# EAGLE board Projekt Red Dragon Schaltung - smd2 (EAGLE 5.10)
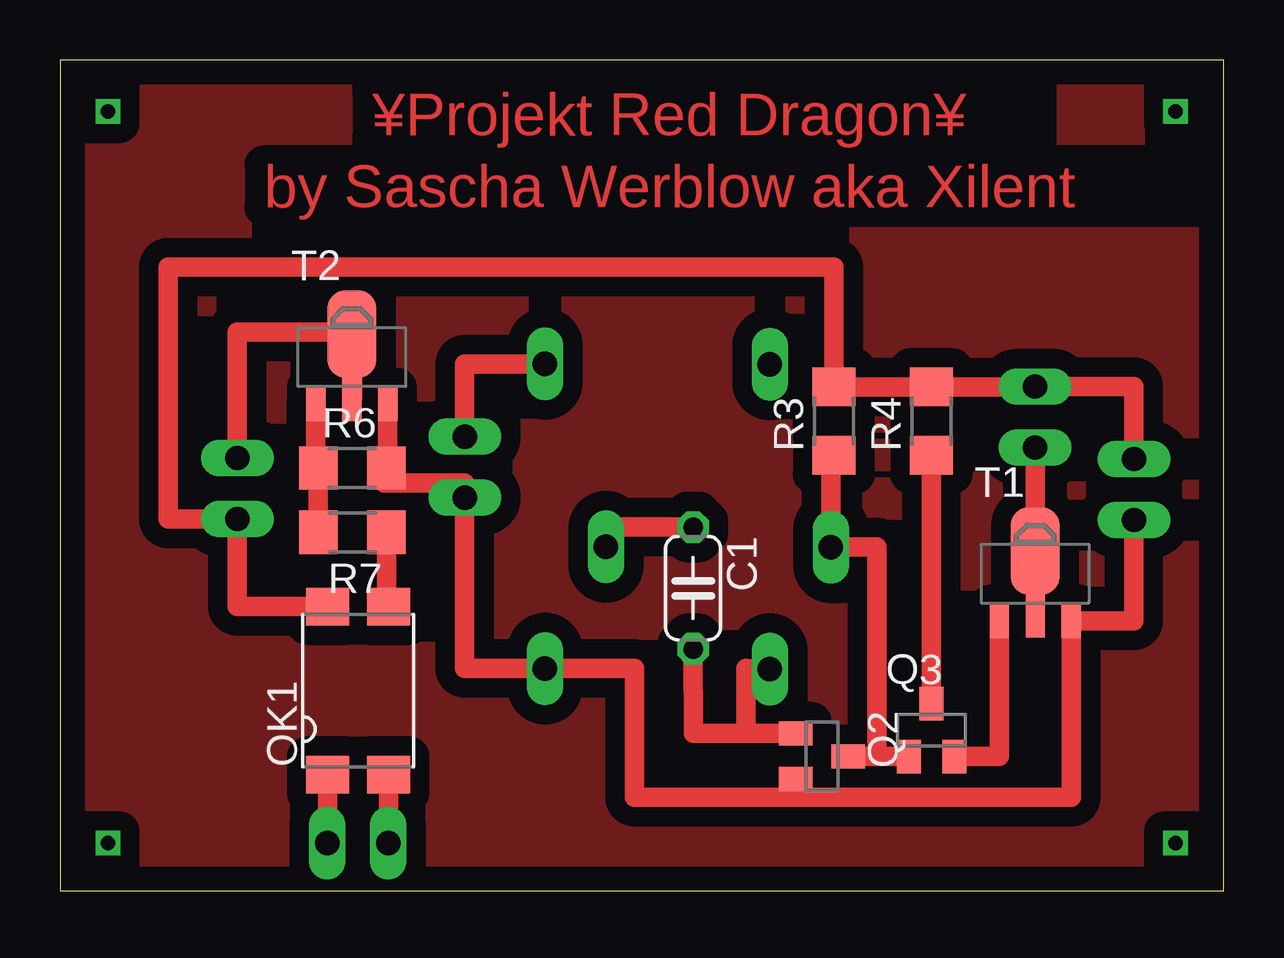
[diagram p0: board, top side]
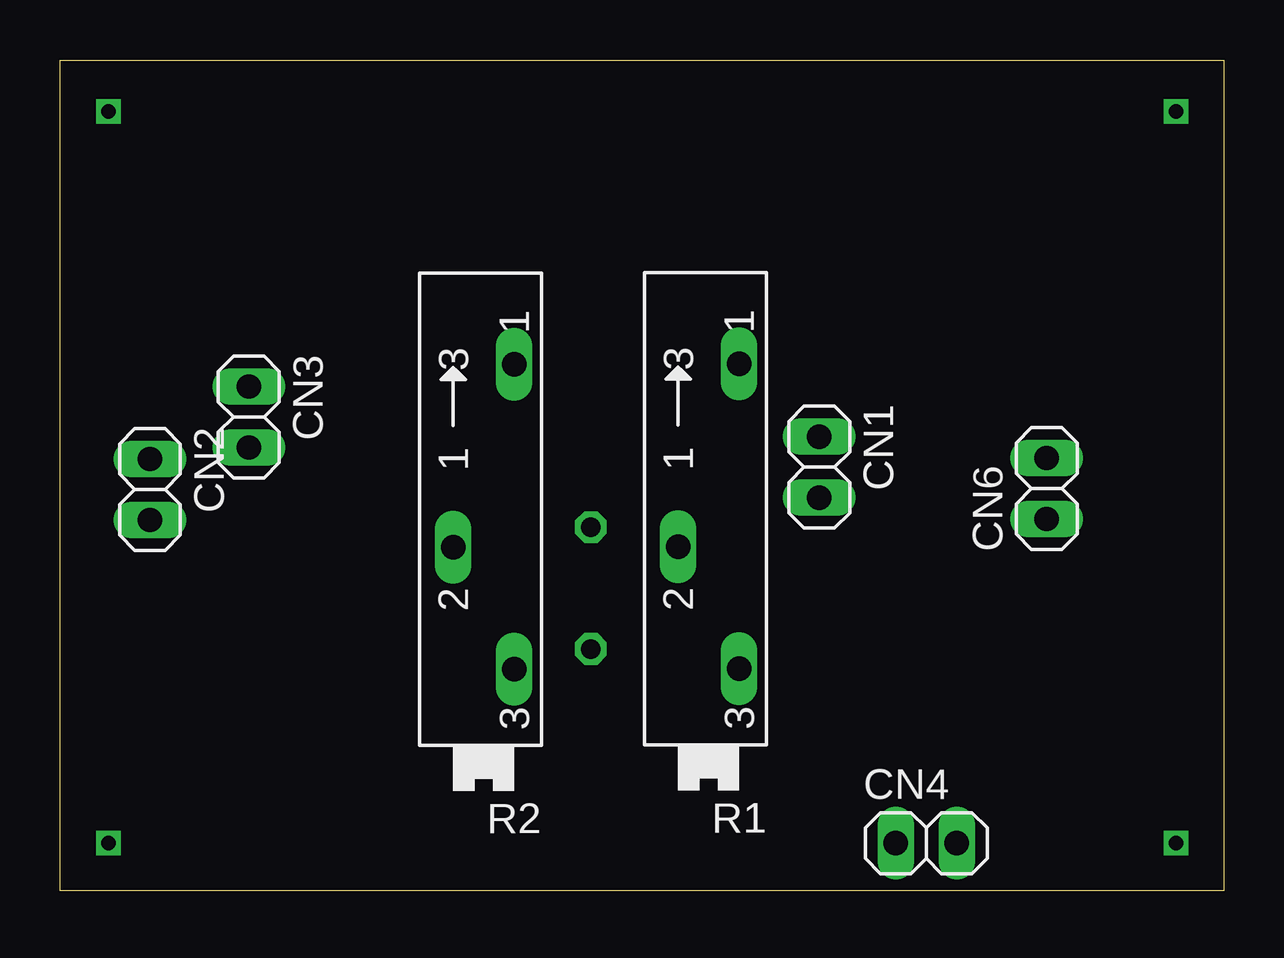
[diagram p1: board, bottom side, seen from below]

Size 48.52 x 34.65 mm. Coordinates in mm from the lower left corner, seen from the top.
Outline: 0,0 48.52,0 48.52,34.65 0,34.65 0,0
Copper layers (1*16): Top 0.035mm / dielectric 1.5mm / Bottom 0.035mm
Design rules "default": minimum track width 10mil, minimum drill 24mil, track to track 8mil, track to pad 8mil, pad to pad 8mil, via to via 8mil, smd to smd 8mil, copper to edge 40mil, drill to drill 8mil, minimum pad ring 10mil, minimum via ring 8mil, stop-mask expansion 4mil, vias tented up to drill 0mil, thermal gap 10mil

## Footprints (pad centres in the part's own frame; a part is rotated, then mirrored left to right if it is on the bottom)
C050-024X044 = drill 0.813 octagon: 1 -2.54,0; 2 2.54,0
1X02 = drill 1.016 long: 1 -1.27,0; 2 1.27,0
SMD4 = smd 1.78 x 1.55: 1 -1.27,-3.5; 2 1.27,-3.5; 3 1.27,3.5; 4 -1.27,3.5
SOT23 = smd 1 x 1.4: 1 -0.95,-1.1; 2 0.95,-1.1; 3 0,1.1
SP19L = drill 1.016 long: A 5.715,-1.27; E -6.985,-1.27; S -1.905,1.27
R1206 = smd 1.6 x 1.803: 1 -1.422,0; 2 1.422,0
SOT89-BCE = smd 0.8 x 1.4: B -1.499,-1.981; E 1.499,-1.981 | smd 0.8 x 1.9: C 0,-1.727 | smd 2.032 x 3.65: C@1 0,0.94

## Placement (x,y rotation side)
C1  330nF  [C050-024X044]  26.39,12.63 270 top
CN1  Audio-In  [1X02]  16.87,17.67 270 bottom
CN2  Power-In  [1X02]  44.77,16.74 270 bottom
CN3  Led-Out  [1X02]  40.65,19.76 270 bottom
CN4  MB-Out  [1X02]  12.41,2 0 bottom
CN6  LED HDD Out  [1X02]  7.39,16.78 90 bottom
OK1  LTV 357T  [SMD4]  12.43,8.36 0 top
Q2  BC848BLT1SMD  [SOT23]  31.76,5.62 270 top
Q3  BC848BLT1SMD  [SOT23]  36.33,6.71 0 top
R1  100K  [SP19L]  21.48,16.26 90 bottom
R2  100K  [SP19L]  30.85,16.24 90 bottom
R3  27K  [R1206]  32.26,19.59 90 top
R4  330  [R1206]  36.32,19.59 90 top
R6  22k  [R1206]  12.18,17.63 0 top
R7  4,7k  [R1206]  12.18,14.95 180 top
T1  BD137  [SOT89-BCE]  40.65,13.24 0 top
T2  BD135  [SOT89-BCE]  12.16,22.27 0 top

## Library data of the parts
C1 R3 R4 R6 R7 = rcl
CN1-CN4 CN6 = pinhead
OK1 = optocoupler
Q2 Q3 = transistor-npn
R1 R2 = pot
T1 T2 = transistor

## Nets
+12V: CN2.1 CN3.1 CN6.1 OK1.4 R3.2 R4.2
GND: CN1.2 CN2.2 Q2.2 R1.E R6.2 T1.E T2.E
N$1: C1.1 R1.S
N$2: C1.2 Q2.1 R2.E
N$3: Q2.3 Q3.1 R2.S R3.1
N$4: Q3.3 R4.1
N$5: Q3.2 T1.B
N$7: R6.1 R7.2 T2.B
N$8: CN4.2 OK1.1
N$9: CN3.2 T1.C
N$10: OK1.3 R7.1
N$11: CN4.1 OK1.2
N$13: CN6.2 T2.C
SIGNAL: CN1.1 R1.A

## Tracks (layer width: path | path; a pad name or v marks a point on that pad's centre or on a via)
+12V
  Top 0.254: R4.2 35.57,20.86
  Top 0.61: 40.65,21.01 CN3.1
  Top 0.813: CN2.1 44.77,21.03 CN3.1 | OK1.4 7.39,11.86 CN6.1 4.5,15.51 4.5,26 32.26,26 R3.2 R4.2 40.65,21.01
GND
  Top 0.813: CN2.2 44.77,11.26 T1.E 42.15,3.9 30.71,3.9 | T2.E 13.65,18.35 13.61,18.35 R6.2 13.5,17.63 13.5,17 16.87,17 CN1.2 16.87,9.28 R1.E 23.95,9.28 23.95,3.9 30.66,3.9 | 30.71,3.9 Q2.2 30.66,3.9 | 30.66,3.9 30.71,3.9
N$1
  Top 0.813: R1.S 22.75,15.17 C1.1
N$2
  Top 0.813: 28.59,6.57 26.41,6.57 C1.2 | 28.59,6.57 Q2.1 | R2.E 28.59,9.28 28.59,6.57
N$3
  Top 0.813: R3.1 32.12,18.17 R2.S 34.05,14.34 34.05,5.62 | 34.05,5.62 Q3.1 | 34.05,5.62 Q2.3
N$4
  Top 0.813: Q3.3 R4.1
N$5
  Top 0.813: Q3.2 39.15,5.61 T1.B
N$6  (via drill 0.6)
  other vias: 2,32.5
N$7
  Top 0.813: R7.2 R6.1 10.76,18.25 10.65,18.25 10.65,20.29 T2.B
N$8
  Top 0.813: CN4.2 11.16,2 OK1.1
N$9
  Top 0.813: T1.C CN3.2
N$10
  Top 0.813: R7.1 13.61,11.86 OK1.3
N$11
  Top 0.813: CN4.1 13.7,2 OK1.2
N$12  (via drill 0.6)
  other vias: 2,2
N$13
  Top 0.813: T2.C 12.2,20.55 12.2,23.3 7.39,23.3 CN6.2
N$14  (via drill 0.6)
  other vias: 46.5,2
N$15  (via drill 0.6)
  other vias: 46.5,32.5
S$1
  pour Top (isolate 0.813): 0,34.5 48.5,34.5 48.5,0 0,0
SIGNAL
  Top 0.813: CN1.1 16.87,21.98 R1.A

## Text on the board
Top: ¥Projekt Red Dragon¥ | by Sascha Werblow aka Xilent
